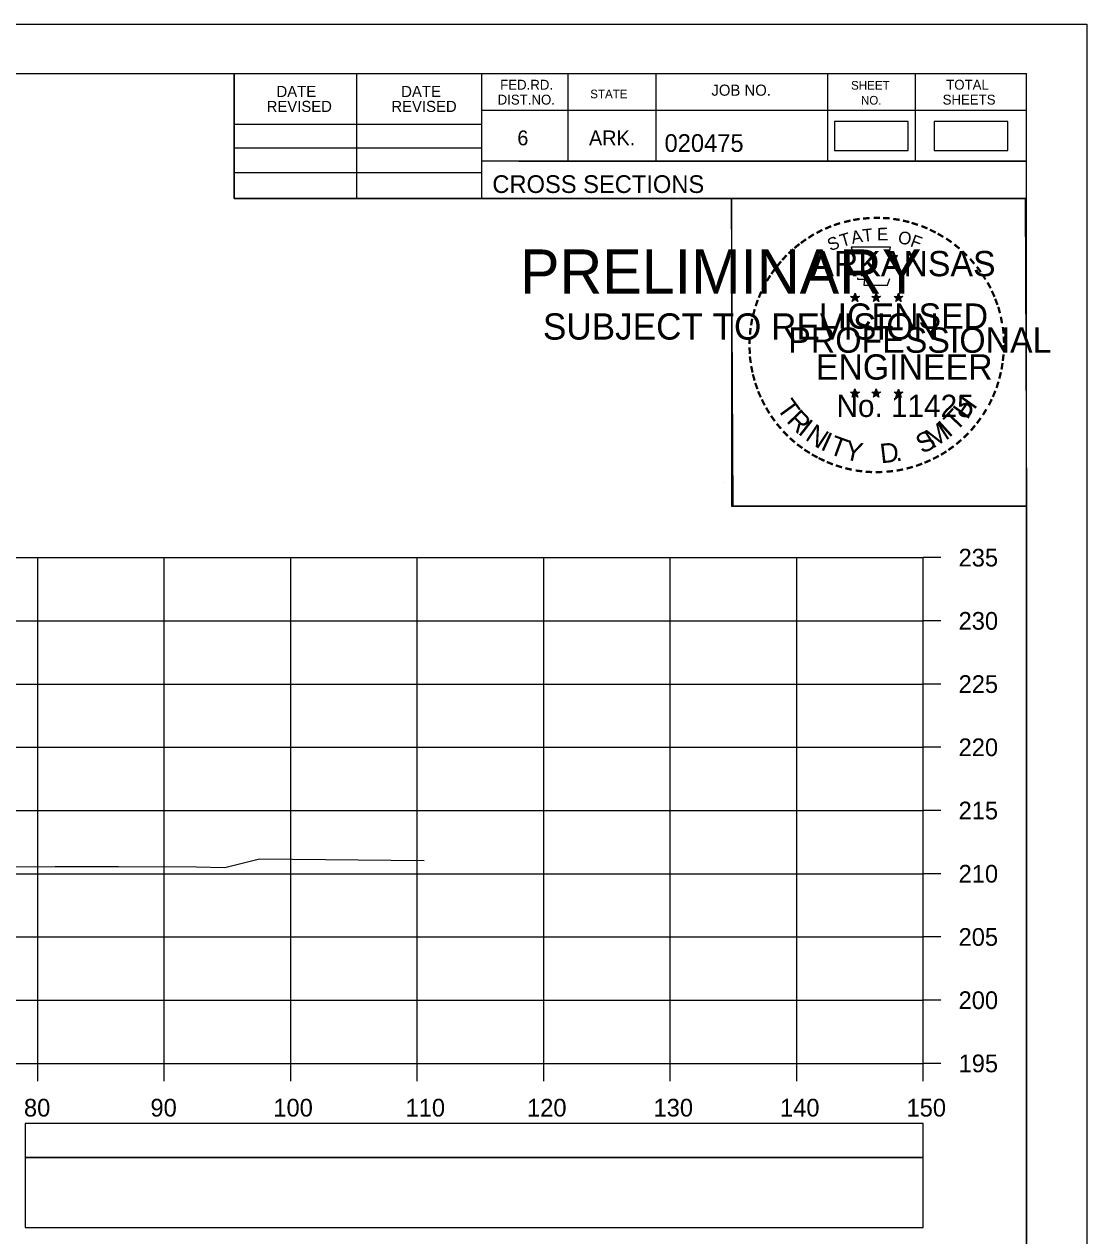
# Model space of a CAD drawing. Extents: x 1386544 to 1388153, y 379785 to 390999.
# Drawn here: x 1387438.6 to 1387522.6, y 386636.4 to 386732.2 of the extents above; entities that cross this region are included whole.
import ezdxf

# ---------------------------------------------------------------- set-up
doc = ezdxf.new("R2010")
doc.units = 0
for name, color, linetype in [('R_Axis', 7, 'Continuous'), ('R_Axis Annot', 7, 'Continuous'), ('R_Border', 7, 'Continuous'), ('R_Border PE', 7, 'Continuous'), ('R_Border Prem', 7, 'Continuous'), ('R_Exist Surface', 7, 'Continuous'), ('R_Grid', 7, 'Continuous'), ('R_No Plot', 7, 'Continuous'), ('S_SHOULDER', 7, 'Continuous')]:
    doc.layers.add(name, color=color, linetype=linetype)

msp = doc.modelspace()

# ---------------------------------------------------------------- linework, layer by layer
at = {"layer": 'R_Axis'}
for p, q in [((1387509.676, 386649.996), (1387509.676, 386689.996)), ((1387511.076, 386689.996), (1387509.676, 386689.996)), ((1387511.076, 386684.996), (1387509.676, 386684.996)), ((1387511.076, 386679.996), (1387509.676, 386679.996)), ((1387511.076, 386674.996), (1387509.676, 386674.996)), ((1387511.076, 386669.996), (1387509.676, 386669.996)), ((1387511.076, 386664.996), (1387509.676, 386664.996)), ((1387511.076, 386659.996), (1387509.676, 386659.996)), ((1387511.076, 386654.996), (1387509.676, 386654.996)), ((1387209.676, 386649.996), (1387509.676, 386649.996)), ((1387439.676, 386648.596), (1387439.676, 386649.996)), ((1387449.676, 386648.596), (1387449.676, 386649.996)), ((1387459.676, 386648.596), (1387459.676, 386649.996)), ((1387469.676, 386648.596), (1387469.676, 386649.996)), ((1387479.676, 386648.596), (1387479.676, 386649.996)), ((1387489.676, 386648.596), (1387489.676, 386649.996)), ((1387499.676, 386648.596), (1387499.676, 386649.996)), ((1387509.676, 386648.596), (1387509.676, 386649.996)), ((1387511.076, 386649.996), (1387509.676, 386649.996))]:
    msp.add_line(p, q, dxfattribs=at)
at = {"layer": 'R_Axis Annot'}
for points in [[(1387438.697, 386642.547), (1387509.676, 386642.547), (1387509.676, 386645.256), (1387438.697, 386645.256)], [(1387438.697, 386637.02), (1387509.676, 386637.02), (1387509.676, 386642.547), (1387438.697, 386642.547)]]:
    msp.add_lwpolyline(points, close=True, dxfattribs=at)
at = {"layer": 'R_Border'}
for p, q in [((1387201.676, 386728.285), (1387517.856, 386728.285)), ((1387455.216, 386718.405), (1387455.216, 386728.285)), ((1387464.896, 386718.405), (1387464.896, 386728.285)), ((1387474.756, 386728.285), (1387474.756, 386718.405)), ((1387481.596, 386728.285), (1387481.596, 386721.345)), ((1387488.536, 386728.285), (1387488.536, 386721.345)), ((1387502.116, 386728.285), (1387502.116, 386721.345)), ((1387509.056, 386728.285), (1387509.056, 386721.345)), ((1387517.856, 386522.825), (1387517.856, 386728.285)), ((1387517.856, 386725.345), (1387474.756, 386725.345)), ((1387517.856, 386725.365), (1387517.856, 386725.365)), ((1387455.216, 386724.265), (1387474.756, 386724.265)), ((1387455.216, 386722.405), (1387474.756, 386722.405)), ((1387517.856, 386721.345), (1387474.756, 386721.345)), ((1387477.716, 386721.345), (1387517.856, 386721.345)), ((1387455.216, 386720.465), (1387474.756, 386720.465)), ((1387517.856, 386718.405), (1387455.216, 386718.405))]:
    msp.add_line(p, q, dxfattribs=at)
at = {"layer": 'R_Border PE'}
for p, q in [((1387504.29, 386710.914), (1387504.249, 386710.662)), ((1387504.29, 386710.549), (1387504.29, 386710.914)), ((1387504.29, 386710.914), (1387504.339, 386710.664)), ((1387505.96, 386710.914), (1387505.919, 386710.662)), ((1387505.96, 386710.549), (1387505.96, 386710.914)), ((1387505.96, 386710.914), (1387506.009, 386710.664)), ((1387507.724, 386710.902), (1387507.683, 386710.65)), ((1387507.724, 386710.537), (1387507.724, 386710.902)), ((1387507.724, 386710.902), (1387507.773, 386710.652)), ((1387503.941, 386710.66), (1387504.29, 386710.549)), ((1387503.941, 386710.66), (1387504.194, 386710.615)), ((1387503.941, 386710.66), (1387504.178, 386710.538)), ((1387504.074, 386710.252), (1387504.29, 386710.549)), ((1387504.074, 386710.252), (1387504.2, 386710.496)), ((1387504.074, 386710.252), (1387504.288, 386710.469)), ((1387504.503, 386710.252), (1387504.288, 386710.466)), ((1387504.637, 386710.66), (1387504.29, 386710.549)), ((1387504.503, 386710.252), (1387504.29, 386710.549)), ((1387504.637, 386710.66), (1387504.351, 386710.611)), ((1387504.503, 386710.252), (1387504.366, 386710.543)), ((1387504.637, 386710.66), (1387504.433, 386710.558)), ((1387505.611, 386710.66), (1387505.96, 386710.549)), ((1387505.611, 386710.66), (1387505.864, 386710.615)), ((1387505.611, 386710.66), (1387505.848, 386710.538)), ((1387505.744, 386710.252), (1387505.96, 386710.549)), ((1387505.744, 386710.252), (1387505.87, 386710.496)), ((1387505.744, 386710.252), (1387505.958, 386710.469)), ((1387506.173, 386710.252), (1387505.958, 386710.466)), ((1387506.307, 386710.66), (1387505.96, 386710.549)), ((1387506.173, 386710.252), (1387505.96, 386710.549)), ((1387506.307, 386710.66), (1387506.021, 386710.611)), ((1387506.173, 386710.252), (1387506.036, 386710.543)), ((1387506.307, 386710.66), (1387506.103, 386710.558)), ((1387507.375, 386710.648), (1387507.724, 386710.537)), ((1387507.375, 386710.648), (1387507.628, 386710.603)), ((1387507.375, 386710.648), (1387507.612, 386710.526)), ((1387507.508, 386710.24), (1387507.724, 386710.537)), ((1387507.508, 386710.24), (1387507.634, 386710.484)), ((1387507.508, 386710.24), (1387507.722, 386710.457)), ((1387507.937, 386710.24), (1387507.722, 386710.454)), ((1387508.071, 386710.648), (1387507.724, 386710.537)), ((1387507.937, 386710.24), (1387507.724, 386710.537)), ((1387508.071, 386710.648), (1387507.785, 386710.599)), ((1387507.937, 386710.24), (1387507.8, 386710.531)), ((1387508.071, 386710.648), (1387507.867, 386710.546)), ((1387503.937, 386703.087), (1387504.286, 386702.976)), ((1387503.937, 386703.087), (1387504.19, 386703.042)), ((1387503.937, 386703.087), (1387504.174, 386702.965)), ((1387504.286, 386703.341), (1387504.245, 386703.089)), ((1387504.286, 386702.976), (1387504.286, 386703.341)), ((1387504.286, 386703.341), (1387504.335, 386703.091)), ((1387504.633, 386703.087), (1387504.286, 386702.976)), ((1387504.633, 386703.087), (1387504.347, 386703.038)), ((1387504.633, 386703.087), (1387504.429, 386702.985)), ((1387505.606, 386703.087), (1387505.955, 386702.976)), ((1387505.606, 386703.087), (1387505.859, 386703.042)), ((1387505.606, 386703.087), (1387505.843, 386702.965)), ((1387505.955, 386703.341), (1387505.914, 386703.089)), ((1387505.955, 386702.976), (1387505.955, 386703.341)), ((1387505.955, 386703.341), (1387506.004, 386703.091)), ((1387506.302, 386703.087), (1387505.955, 386702.976)), ((1387506.302, 386703.087), (1387506.016, 386703.038)), ((1387506.302, 386703.087), (1387506.098, 386702.985)), ((1387507.373, 386703.077), (1387507.722, 386702.966)), ((1387507.373, 386703.077), (1387507.626, 386703.032)), ((1387507.373, 386703.077), (1387507.61, 386702.955)), ((1387507.722, 386703.331), (1387507.681, 386703.079)), ((1387507.722, 386702.966), (1387507.722, 386703.331)), ((1387507.722, 386703.331), (1387507.771, 386703.081)), ((1387508.069, 386703.077), (1387507.722, 386702.966)), ((1387508.069, 386703.077), (1387507.783, 386703.028)), ((1387508.069, 386703.077), (1387507.865, 386702.975)), ((1387504.07, 386702.679), (1387504.286, 386702.976)), ((1387504.07, 386702.679), (1387504.196, 386702.923)), ((1387504.07, 386702.679), (1387504.284, 386702.896)), ((1387504.499, 386702.679), (1387504.284, 386702.893)), ((1387504.499, 386702.679), (1387504.286, 386702.976)), ((1387504.499, 386702.679), (1387504.362, 386702.97)), ((1387505.739, 386702.679), (1387505.955, 386702.976)), ((1387505.739, 386702.679), (1387505.865, 386702.923)), ((1387505.739, 386702.679), (1387505.953, 386702.896)), ((1387506.168, 386702.679), (1387505.953, 386702.893)), ((1387506.168, 386702.679), (1387505.955, 386702.976)), ((1387506.168, 386702.679), (1387506.031, 386702.97)), ((1387507.506, 386702.669), (1387507.722, 386702.966)), ((1387507.506, 386702.669), (1387507.632, 386702.913)), ((1387507.506, 386702.669), (1387507.72, 386702.886)), ((1387507.935, 386702.669), (1387507.72, 386702.883)), ((1387507.935, 386702.669), (1387507.722, 386702.966)), ((1387507.935, 386702.669), (1387507.798, 386702.96))]:
    msp.add_line(p, q, dxfattribs=at)
for points in [[(1387503.982, 386714.538), (1387504.251, 386713.711)], [(1387507.493, 386713.616), (1387507.635, 386713.9), (1387506.95, 386713.876), (1387507.098, 386714.538), (1387503.982, 386714.538)], [(1387504.474, 386712.115), (1387504.474, 386712.028), (1387505.037, 386712.009), (1387504.983, 386711.536), (1387506.853, 386711.536), (1387507.054, 386712.072)], [(1387504.29, 386710.914), (1387504.503, 386710.252), (1387503.941, 386710.66), (1387504.637, 386710.66), (1387504.074, 386710.252), (1387504.29, 386710.914)], [(1387505.96, 386710.914), (1387506.173, 386710.252), (1387505.611, 386710.66), (1387506.307, 386710.66), (1387505.744, 386710.252), (1387505.96, 386710.914)], [(1387507.724, 386710.902), (1387507.937, 386710.24), (1387507.375, 386710.648), (1387508.071, 386710.648), (1387507.508, 386710.24), (1387507.724, 386710.902)], [(1387504.286, 386703.341), (1387504.499, 386702.679), (1387503.937, 386703.087), (1387504.633, 386703.087), (1387504.07, 386702.679), (1387504.286, 386703.341)], [(1387505.955, 386703.341), (1387506.168, 386702.679), (1387505.606, 386703.087), (1387506.302, 386703.087), (1387505.739, 386702.679), (1387505.955, 386703.341)], [(1387507.722, 386703.331), (1387507.935, 386702.669), (1387507.373, 386703.077), (1387508.069, 386703.077), (1387507.506, 386702.669), (1387507.722, 386703.331)]]:
    msp.add_lwpolyline(points, dxfattribs=at)
for centre, radius in [((1387504.289, 386710.548), 0.172), ((1387504.289, 386710.548), 0.145), ((1387505.959, 386710.548), 0.172), ((1387505.959, 386710.548), 0.145), ((1387507.723, 386710.536), 0.172), ((1387504.289, 386710.548), 0.116), ((1387504.289, 386710.548), 0.0991), ((1387504.289, 386710.548), 0.0747), ((1387504.289, 386710.548), 0.0495), ((1387504.289, 386710.548), 0.0296), ((1387505.959, 386710.548), 0.116), ((1387505.959, 386710.548), 0.0991), ((1387505.959, 386710.548), 0.0747), ((1387505.959, 386710.548), 0.0495), ((1387505.959, 386710.548), 0.0296), ((1387507.723, 386710.536), 0.145), ((1387507.723, 386710.536), 0.116), ((1387507.723, 386710.536), 0.0991), ((1387507.723, 386710.536), 0.0747), ((1387507.723, 386710.536), 0.0495), ((1387507.723, 386710.536), 0.0296), ((1387504.285, 386702.975), 0.172), ((1387504.285, 386702.975), 0.145), ((1387504.285, 386702.975), 0.116), ((1387504.285, 386702.975), 0.0991), ((1387504.285, 386702.975), 0.0747), ((1387505.954, 386702.975), 0.172), ((1387505.954, 386702.975), 0.145), ((1387505.954, 386702.975), 0.116), ((1387505.954, 386702.975), 0.0991), ((1387505.954, 386702.975), 0.0747), ((1387507.721, 386702.965), 0.172), ((1387507.721, 386702.965), 0.145), ((1387507.721, 386702.965), 0.116), ((1387507.721, 386702.965), 0.0991), ((1387507.721, 386702.965), 0.0747), ((1387504.285, 386702.975), 0.0495), ((1387504.285, 386702.975), 0.0296), ((1387505.954, 386702.975), 0.0495), ((1387505.954, 386702.975), 0.0296), ((1387507.721, 386702.965), 0.0495), ((1387507.721, 386702.965), 0.0296)]:
    msp.add_circle(centre, radius, dxfattribs=at)
at = {"layer": 'R_Exist Surface'}
msp.add_lwpolyline([(1387432.816, 386665.546), (1387441.063, 386665.561), (1387446.066, 386665.58), (1387452.241, 386665.545), (1387454.467, 386665.503), (1387457.218, 386666.177), (1387470.234, 386666.051)], dxfattribs=at)
at = {"layer": 'R_Grid'}
for p, q in [((1387209.676, 386689.996), (1387509.676, 386689.996)), ((1387439.676, 386649.996), (1387439.676, 386689.996)), ((1387449.676, 386649.996), (1387449.676, 386689.996)), ((1387459.676, 386649.996), (1387459.676, 386689.996)), ((1387469.676, 386649.996), (1387469.676, 386689.996)), ((1387479.676, 386649.996), (1387479.676, 386689.996)), ((1387489.676, 386649.996), (1387489.676, 386689.996)), ((1387499.676, 386649.996), (1387499.676, 386689.996)), ((1387509.676, 386649.996), (1387509.676, 386689.996)), ((1387209.676, 386684.996), (1387509.676, 386684.996)), ((1387209.676, 386679.996), (1387509.676, 386679.996)), ((1387209.676, 386674.996), (1387509.676, 386674.996)), ((1387209.676, 386669.996), (1387509.676, 386669.996)), ((1387209.676, 386664.996), (1387509.676, 386664.996)), ((1387209.676, 386659.996), (1387509.676, 386659.996)), ((1387209.676, 386654.996), (1387509.676, 386654.996)), ((1387209.676, 386649.996), (1387509.676, 386649.996))]:
    msp.add_line(p, q, dxfattribs=at)
at = {"layer": 'R_No Plot'}
for p, q in [((1387189.275, 386732.179), (1387522.609, 386732.179)), ((1387493.89, 386695.949), (1387493.89, 386695.949))]:
    msp.add_line(p, q, dxfattribs=at)
for points in [[(1387189.269, 386732.179), (1387522.609, 386732.179), (1387522.609, 386518.842), (1387189.269, 386518.842)], [(1387435.596, 386728.285), (1387455.216, 386728.285), (1387455.216, 386718.405), (1387471.328, 386718.405), (1387494.528, 386718.405), (1387494.528, 386694.072), (1387517.856, 386694.072), (1387517.856, 386522.825), (1387201.676, 386522.825), (1387201.676, 386728.285)], [(1387494.528, 386718.405), (1387517.735, 386718.405), (1387517.856, 386694.072), (1387494.648, 386694.072)]]:
    msp.add_lwpolyline(points, close=True, dxfattribs=at)
at = {"layer": 'S_SHOULDER'}
for points in [[(1387502.669, 386722.19), (1387508.503, 386722.19), (1387508.503, 386724.5), (1387502.669, 386724.5)], [(1387510.539, 386722.19), (1387516.373, 386722.19), (1387516.373, 386724.5), (1387510.539, 386724.5)]]:
    msp.add_lwpolyline(points, close=True, dxfattribs=at)

# ---------------------------------------------------------------- texts
at = {"layer": 'R_Axis Annot'}
for s, p in [('235', (1387512.476, 386689.296)), ('230', (1387512.476, 386684.296)), ('225', (1387512.476, 386679.296)), ('220', (1387512.476, 386674.296)), ('215', (1387512.476, 386669.296)), ('210', (1387512.476, 386664.296)), ('205', (1387512.476, 386659.296)), ('200', (1387512.476, 386654.296)), ('195', (1387512.476, 386649.296)), ('80', (1387438.59, 386645.796)), ('90', (1387448.59, 386645.796)), ('100', (1387458.304, 386645.796)), ('110', (1387468.756, 386645.796)), ('120', (1387478.359, 386645.796)), ('130', (1387488.359, 386645.796)), ('140', (1387498.359, 386645.796)), ('150', (1387508.359, 386645.796))]:
    msp.add_text(s, height=1.4, dxfattribs=at).set_placement(p)
at = {"layer": 'R_Border'}
for s, height, p in [('DATE', 0.8792, (1387458.554, 386726.421)), ('DATE', 0.8792, (1387468.414, 386726.421)), ('FED.RD.', 0.7819, (1387476.236, 386727.005)), ('STATE', 0.684, (1387483.356, 386726.325)), ('JOB NO.', 0.8792, (1387492.936, 386726.525)), ('SHEET', 0.684, (1387503.976, 386727.005)), ('TOTAL', 0.7819, (1387511.496, 386727.005)), ('REVISED', 0.8792, (1387457.774, 386725.241)), ('REVISED', 0.8792, (1387467.634, 386725.241)), ('DIST.NO.', 0.7819, (1387476.036, 386725.825)), ('NO.', 0.684, (1387504.756, 386725.825)), ('SHEETS', 0.7819, (1387511.216, 386725.825)), ('6', 1.172, (1387477.596, 386722.605)), ('ARK.', 1.1723, (1387483.256, 386722.605)), ('020475', 1.4, (1387489.232, 386722.084)), ('CROSS SECTIONS', 1.4, (1387475.62, 386718.835))]:
    msp.add_text(s, height=height, rotation=360, dxfattribs=at).set_placement(p)
at = {"layer": 'R_Border PE'}
for s, height, rotation, p in [('-', 1.6, 19.17608, (1387502.73, 386715.665)), ('-', 1.6, 13.63015, (1387503.48, 386715.906)), ('-', 1.6, 10.21935, (1387504.158, 386716.068)), ('-', 1.6, 5.89682, (1387504.887, 386716.178)), ('-', 1.6, 0.18623, (1387505.659, 386716.25)), ('-', 1.6, 357.74304, (1387506.382, 386716.237)), ('-', 1.6, 352.16172, (1387507.126, 386716.181)), ('-', 1.6, 347.20489, (1387507.845, 386716.067)), ('-', 1.6, 342.3362, (1387508.48, 386715.912)), ('-', 1.6, 34.06357, (1387500.866, 386714.709)), ('-', 1.6, 28.79182, (1387501.463, 386715.079)), ('-', 1.6, 24.30721, (1387502.096, 386715.396)), ('T', 1, 16.4036, (1387503.251, 386714.547)), ('A', 1, 11.21318, (1387504.077, 386714.798)), ('T', 1, 6.02276, (1387504.926, 386714.964)), ('E', 1, 0.83234, (1387506.031, 386715.074)), ('O', 1, 350.4515, (1387507.635, 386714.864)), ('F', 1, 340.07066, (1387508.589, 386714.636)), ('-', 1.6, 337.85509, (1387509.215, 386715.689)), ('-', 1.6, 334.12109, (1387509.846, 386715.418)), ('-', 1.6, 329.64089, (1387510.425, 386715.135)), ('-', 1.6, 38.95066, (1387499.812, 386713.936)), ('-', 1.6, 36.23174, (1387500.288, 386714.314)), ('S', 1, 21.59401, (1387502.337, 386714.216)), ('-', 1.6, 325.86266, (1387511.068, 386714.774)), ('-', 1.6, 320.52971, (1387511.678, 386714.348)), ('-', 1.6, 48.42305, (1387498.931, 386713.041)), ('-', 1.6, 42.96224, (1387499.379, 386713.519)), ('ARKANSAS', 2, 360, (1387500.835, 386712.25)), ('-', 1.6, 315.57859, (1387512.277, 386713.86)), ('-', 1.6, 309.87973, (1387512.846, 386713.31)), ('-', 1.6, 54.23247, (1387498.115, 386711.988)), ('-', 1.6, 50.61417, (1387498.528, 386712.555)), ('-', 1.6, 306.65218, (1387513.371, 386712.708)), ('-', 1.6, 62.87135, (1387497.477, 386710.847)), ('-', 1.6, 58.07063, (1387497.79, 386711.461)), ('-', 1.4, 303.67529, (1387513.857, 386712.14)), ('-', 1.6, 299.66835, (1387514.176, 386711.533)), ('-', 1.6, 67.77427, (1387497.218, 386710.236)), ('-', 1.6, 294.66279, (1387514.5, 386710.921)), ('-', 1.6, 72.39447, (1387496.999, 386709.606)), ('LICENSED', 2, 360, (1387501.432, 386708.101)), ('DWB', 0.01, 360, (1387504.277, 386710.544)), ('DWB', 0.01, 360, (1387505.947, 386710.544)), ('DWB', 0.01, 360, (1387507.711, 386710.533)), ('-', 1.6, 290.57283, (1387514.757, 386710.344)), ('-', 1.6, 285.12326, (1387514.991, 386709.764)), ('-', 1.6, 81.20126, (1387496.67, 386708.179)), ('-', 1.6, 75.46096, (1387496.802, 386708.892)), ('-', 1.6, 280.54934, (1387515.191, 386709.022)), ('-', 1.6, 85.18634, (1387496.594, 386707.488)), ('PROFESSIONAL', 2, 360, (1387499.009, 386706.197)), ('-', 1.6, 276.59616, (1387515.353, 386708.254)), ('-', 1.6, 89.06224, (1387496.569, 386706.787)), ('-', 1.6, 274.33011, (1387515.413, 386707.532)), ('-', 1.6, 94.19588, (1387496.604, 386706.062)), ('-', 1.6, 98.94793, (1387496.676, 386705.395)), ('ENGINEER', 2, 360, (1387501.196, 386704.072)), ('-', 1.6, 263.5172, (1387515.428, 386706.234)), ('-', 1.6, 269.94067, (1387515.447, 386706.9)), ('-', 1.6, 101.71495, (1387496.811, 386704.662)), ('-', 1.6, 260.99529, (1387515.357, 386705.58)), ('-', 1.6, 105.45785, (1387496.973, 386704.067)), ('-', 1.6, 255.7626, (1387515.247, 386704.902)), ('-', 1.6, 109.08742, (1387497.188, 386703.436)), ('-', 1.6, 114.06432, (1387497.442, 386702.84)), ('-', 1.6, 247.88866, (1387514.843, 386703.509)), ('-', 1.6, 252.86809, (1387515.066, 386704.182)), ('-', 1.6, 115.72885, (1387497.747, 386702.222)), ('T', 1.54, 306.04056, (1387498.046, 386701.814)), ('No. 11425', 1.757, 360, (1387502.823, 386701.121)), ('DWB', 0.01, 360, (1387504.273, 386702.971)), ('DWB', 0.01, 360, (1387505.942, 386702.971)), ('DWB', 0.01, 360, (1387507.709, 386702.961)), ('H', 1.54, 54.60883, (1387513.166, 386700.849)), ('-', 1.6, 244.61971, (1387514.581, 386702.88)), ('-', 1.6, 120.44712, (1387498.104, 386701.636)), ('-', 1.6, 125.89344, (1387498.507, 386701.075)), ('R', 1.54, 314.00497, (1387498.808, 386700.766)), ('T', 1.54, 46.64442, (1387512.276, 386699.907)), ('-', 1.6, 239.07125, (1387514.187, 386702.128)), ('-', 1.6, 130.71812, (1387498.969, 386700.523)), ('I', 1.54, 321.96938, (1387499.709, 386699.834)), ('N', 1.54, 326.50021, (1387500.276, 386699.363)), ('M', 1.54, 32.65632, (1387510.43, 386698.582)), ('I', 1.54, 42.11359, (1387511.715, 386699.429)), ('-', 1.6, 231.25377, (1387513.355, 386700.909)), ('-', 1.6, 233.84524, (1387513.785, 386701.475)), ('-', 1.6, 134.22381, (1387499.486, 386699.978)), ('-', 1.6, 138.93382, (1387500.011, 386699.514)), ('I', 1.54, 335.36034, (1387501.484, 386698.577)), ('T', 1.54, 339.89117, (1387502.145, 386698.249)), ('Y', 1.54, 347.85558, (1387503.362, 386697.804)), ('S', 1.54, 26.9312, (1387509.592, 386698.176)), ('-', 1.6, 221.08509, (1387512.354, 386699.836)), ('-', 1.6, 225.76533, (1387512.876, 386700.345)), ('-', 1.6, 144.64634, (1387500.567, 386699.108)), ('-', 1.6, 148.08978, (1387501.128, 386698.737)), ('-', 1.6, 151.57039, (1387501.707, 386698.412)), ('D', 1.54, 6.39691, (1387506.347, 386697.445)), ('-', 1.6, 212.24909, (1387511.271, 386698.977)), ('-', 1.6, 215.73633, (1387511.805, 386699.364)), ('-', 1.6, 154.60019, (1387502.229, 386698.165)), ('-', 1.6, 158.56121, (1387502.853, 386697.911)), ('-', 1.6, 162.79826, (1387503.54, 386697.698)), ('.', 1.54, 13.76417, (1387507.539, 386697.573)), ('-', 1.6, 200.71842, (1387509.47, 386698.039)), ('-', 1.6, 204.25161, (1387510.089, 386698.312)), ('-', 1.6, 207.35684, (1387510.713, 386698.631)), ('-', 1.6, 167.55551, (1387504.255, 386697.534)), ('-', 1.6, 173.11546, (1387505.027, 386697.424)), ('-', 1.6, 176.51827, (1387505.775, 386697.371)), ('-', 1.6, 181.59176, (1387506.519, 386697.39)), ('-', 1.6, 185.81666, (1387507.328, 386697.466)), ('-', 1.6, 191.28576, (1387508.064, 386697.598)), ('-', 1.6, 195.47429, (1387508.793, 386697.797))]:
    msp.add_text(s, height=height, rotation=rotation, dxfattribs=at).set_placement(p)
at = {"layer": 'R_Border Prem'}
for s, height, p in [('PRELIMINARY', 3.5, (1387477.807, 386710.868)), ('DWB', 0.01, (1387478.554, 386712.717)), ('SUBJECT TO REVISION', 2.07511, (1387479.616, 386707.239))]:
    msp.add_text(s, height=height, rotation=360, dxfattribs=at).set_placement(p)

doc.saveas('drawing.dxf')
